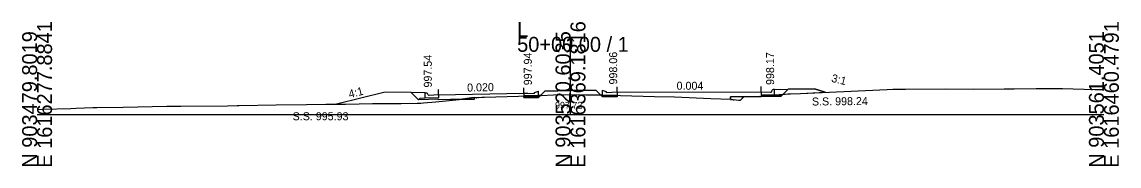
# Model space of a CAD drawing. Extents: x 1009 to 7438, y -1586 to 7964.
# Drawn here: x 4032.1 to 4237.7, y 7914 to 7941.1 of the extents above; entities that cross this region are included whole.
import ezdxf

# ---------------------------------------------------------------- set-up
doc = ezdxf.new("R2010")
doc.units = 0
for name, color, linetype in [('Exist Cross Section Cell', 7, 'Continuous'), ('Exist XS Center Line Elevation Label', 7, 'Continuous'), ('Exist XS Ground Line', 7, 'Continuous'), ('Prop XS Dump Level', 7, 'Continuous'), ('Prop XS Earthwork Shape', 7, 'Continuous'), ('Prop XS EOT Tick Mark', 7, 'Continuous'), ('Prop XS Finish Grade', 7, 'Continuous'), ('Prop XS Finish Grade CurbGutter', 7, 'Continuous'), ('Prop XS Finish Grade Earthwork', 7, 'Continuous'), ('Prop XS Finish Grade Pavement', 7, 'Continuous'), ('Prop XS Hydro Elevations', 7, 'Continuous'), ('Prop XS Pvmt Edge Slope', 7, 'Continuous'), ('Prop XS SE Text', 7, 'Continuous'), ('Prop XS Side Slope Text', 7, 'Continuous'), ('Prop XS SS Elevation Text', 7, 'Continuous'), ('Prop XS Subgrade CurbGutter', 7, 'Continuous'), ('Prop XS Subgrade Earthwork', 7, 'Continuous')]:
    doc.layers.add(name, color=color, linetype=linetype)

msp = doc.modelspace()

# ---------------------------------------------------------------- linework, layer by layer
at = {"layer": 'Exist Cross Section Cell'}
for p, q in [((4134.89, 7923.73), (4134.89, 7938.27)), ((4034.89, 7923.73), (4134.89, 7923.73)), ((4134.89, 7923.73), (4234.89, 7923.73))]:
    msp.add_line(p, q, dxfattribs=at)
at = {"layer": 'Exist XS Ground Line'}
for p, q in [((4118.25, 7926.96), (4118.77, 7926.98)), ((4118.77, 7926.98), (4129.4, 7927.3)), ((4129.4, 7927.3), (4131.69, 7927.38)), ((4131.69, 7927.38), (4134.7, 7927.45)), ((4134.7, 7927.45), (4137.78, 7927.43)), ((4137.78, 7927.43), (4139.99, 7927.41)), ((4139.99, 7927.41), (4150.67, 7927.11)), ((4150.67, 7927.11), (4154.36, 7927.02)), ((4154.36, 7927.02), (4161.2, 7926.73)), ((4166.77, 7926.4), (4167.4, 7927.06)), ((4167.4, 7927.06), (4170.39, 7927.17)), ((4170.39, 7927.17), (4172.79, 7927.25)), ((4172.79, 7927.25), (4175.66, 7927.56)), ((4175.66, 7927.56), (4176.13, 7927.61)), ((4176.13, 7927.61), (4177.99, 7927.67)), ((4177.99, 7927.67), (4194.28, 7928.43)), ((4194.28, 7928.43), (4195.34, 7928.46)), ((4195.34, 7928.46), (4197.71, 7928.49)), ((4197.71, 7928.49), (4205.23, 7928.51)), ((4205.23, 7928.51), (4210.48, 7928.45)), ((4210.48, 7928.45), (4216.19, 7928.5)), ((4216.19, 7928.5), (4218.05, 7928.51)), ((4218.05, 7928.51), (4222.22, 7928.57)), ((4222.22, 7928.57), (4227.14, 7928.58)), ((4227.14, 7928.58), (4233.19, 7928.42)), ((4233.19, 7928.42), (4234.89, 7928.42)), ((4042.22, 7924.89), (4045.33, 7925.01)), ((4045.33, 7925.01), (4046.06, 7925.03)), ((4046.06, 7925.03), (4051.04, 7925.1)), ((4051.04, 7925.1), (4059.21, 7925.26)), ((4059.21, 7925.26), (4061.86, 7925.29)), ((4061.86, 7925.29), (4070.61, 7925.36)), ((4070.61, 7925.36), (4072.4, 7925.4)), ((4072.4, 7925.4), (4072.75, 7925.4)), ((4072.75, 7925.4), (4079.72, 7925.52)), ((4079.72, 7925.52), (4085.37, 7925.6)), ((4085.37, 7925.6), (4089.03, 7925.63)), ((4089.03, 7925.63), (4092.7, 7925.67)), ((4092.7, 7925.67), (4095.28, 7925.7)), ((4095.28, 7925.7), (4097.76, 7925.76)), ((4097.76, 7925.76), (4103.12, 7925.8)), ((4103.12, 7925.8), (4106.15, 7925.81)), ((4106.15, 7925.81), (4106.81, 7925.84)), ((4106.81, 7925.84), (4107.33, 7925.88)), ((4107.33, 7925.88), (4109.67, 7926.08)), ((4109.67, 7926.08), (4114.62, 7926.57)), ((4114.62, 7926.57), (4115.43, 7926.71)), ((4115.43, 7926.71), (4116.32, 7926.81)), ((4116.32, 7926.81), (4116.87, 7926.91)), ((4116.87, 7926.91), (4118.25, 7926.96)), ((4161.2, 7926.73), (4164.91, 7926.61)), ((4164.91, 7926.61), (4166.43, 7926.41)), ((4166.43, 7926.41), (4166.77, 7926.4)), ((4034.89, 7924.66), (4035.88, 7924.69)), ((4035.88, 7924.69), (4041.19, 7924.86)), ((4041.19, 7924.86), (4042.22, 7924.89))]:
    msp.add_line(p, q, dxfattribs=at)
at = {"layer": 'Prop XS Dump Level'}
msp.add_line((4110.14, 7927.39), (4126.14, 7927.71), dxfattribs=at)
msp.add_line((4110.14, 7927.39), (4126.14, 7927.71), dxfattribs=at)
at = {"layer": 'Prop XS Earthwork Shape'}
for points in [[(4109.67, 7926.08), (4114.56, 7926.56), (4110.14, 7926.47), (4110.14, 7926.56), (4106.39, 7926.48), (4105.05, 7927.82), (4100.14, 7927.93), (4091.05, 7925.65), (4092.7, 7925.67), (4095.28, 7925.7), (4097.76, 7925.76), (4103.12, 7925.8), (4106.15, 7925.81), (4106.81, 7925.84), (4107.33, 7925.88)], [(4126.14, 7927.13), (4127.64, 7927.16), (4128.64, 7927.18), (4128.89, 7927.18), (4128.89, 7927.29), (4126.14, 7927.2)], [(4128.64, 7927.18), (4128.89, 7926.93), (4126.14, 7926.88), (4126.14, 7927.13), (4127.64, 7927.16)], [(4128.89, 7926.93), (4129.25, 7927.3), (4128.89, 7927.29), (4128.89, 7927.18), (4128.64, 7927.18)], [(4134.7, 7927.45), (4137.78, 7927.43), (4139.99, 7927.41), (4140.54, 7927.39), (4139.72, 7928.21), (4135, 7928.22), (4130.07, 7928.11), (4129.25, 7927.3), (4129.4, 7927.3), (4131.69, 7927.38)], [(4140.54, 7927.39), (4140.89, 7927.38), (4140.89, 7927.29), (4141.14, 7927.29), (4140.89, 7927.04)], [(4142.14, 7927.29), (4141.14, 7927.29), (4140.89, 7927.29), (4140.89, 7927.38), (4143.64, 7927.31), (4143.64, 7927.29)], [(4143.64, 7927.04), (4140.89, 7927.04), (4141.14, 7927.29), (4142.14, 7927.29), (4143.64, 7927.29)], [(4166.77, 7926.4), (4167.38, 7927.04), (4164.91, 7927.03), (4164.91, 7926.61), (4166.43, 7926.41)], [(4170.64, 7927.14), (4170.64, 7927.06), (4167.38, 7927.04), (4167.4, 7927.06), (4170.39, 7927.17), (4172.79, 7927.25), (4174.04, 7927.39), (4174.14, 7927.39), (4174.39, 7927.14)], [(4174.04, 7927.39), (4174.14, 7927.39), (4174.39, 7927.14), (4174.72, 7927.46)], [(4175.66, 7927.56), (4176.13, 7927.61), (4177.99, 7927.67), (4182.62, 7927.89), (4180.64, 7928.55), (4175.7, 7928.44), (4174.72, 7927.46)], [(4116.87, 7926.61), (4116.87, 7926.91), (4116.32, 7926.81), (4115.43, 7926.71), (4114.62, 7926.57), (4114.56, 7926.56)]]:
    msp.add_lwpolyline(points, close=True, dxfattribs=at)
at = {"layer": 'Prop XS EOT Tick Mark'}
for p, q in [((4110.14, 7927.39), (4110.14, 7928.39)), ((4126.14, 7927.71), (4126.14, 7928.71)), ((4143.64, 7927.87), (4143.64, 7928.87)), ((4170.64, 7927.97), (4170.64, 7928.97))]:
    msp.add_line(p, q, dxfattribs=at)
at = {"layer": 'Prop XS Finish Grade'}
for p, q in [((4107.64, 7927.77), (4105.05, 7927.82)), ((4173.14, 7928.39), (4175.7, 7928.44))]:
    msp.add_line(p, q, dxfattribs=at)
at = {"layer": 'Prop XS Finish Grade CurbGutter'}
for p, q in [((4107.64, 7927.77), (4107.89, 7927.77)), ((4107.89, 7927.77), (4108.02, 7927.74)), ((4108.11, 7927.65), (4108.02, 7927.74)), ((4108.18, 7927.4), (4108.11, 7927.65)), ((4108.27, 7927.31), (4108.18, 7927.4)), ((4108.39, 7927.28), (4108.27, 7927.31)), ((4110.14, 7927.39), (4108.39, 7927.28)), ((4126.14, 7927.71), (4126.89, 7927.69)), ((4126.14, 7927.71), (4128.14, 7927.67)), ((4128.14, 7927.84), (4128.89, 7928.09)), ((4128.14, 7927.67), (4128.14, 7927.84)), ((4141.64, 7927.96), (4140.89, 7928.21)), ((4141.64, 7927.79), (4141.64, 7927.96)), ((4143.64, 7927.87), (4141.64, 7927.79)), ((4143.64, 7927.87), (4142.89, 7927.84)), ((4170.64, 7927.97), (4172.39, 7927.9)), ((4172.39, 7927.9), (4172.52, 7927.92)), ((4172.52, 7927.92), (4172.61, 7928.02)), ((4172.61, 7928.02), (4172.68, 7928.27)), ((4172.68, 7928.27), (4172.77, 7928.36)), ((4172.89, 7928.39), (4172.77, 7928.36)), ((4173.14, 7928.39), (4172.89, 7928.39))]:
    msp.add_line(p, q, dxfattribs=at)
at = {"layer": 'Prop XS Finish Grade Earthwork'}
for p, q in [((4100.14, 7927.93), (4091.05, 7925.65)), ((4105.05, 7927.82), (4100.14, 7927.93)), ((4130.07, 7928.11), (4135, 7928.22)), ((4139.72, 7928.21), (4135, 7928.22)), ((4175.7, 7928.44), (4180.64, 7928.55))]:
    msp.add_line(p, q, dxfattribs=at)
msp.add_lwpolyline([(4180.64, 7928.55), (4182.62, 7927.89)], dxfattribs=at)
at = {"layer": 'Prop XS Finish Grade Pavement'}
for p, q in [((4110.14, 7927.39), (4126.14, 7927.71)), ((4143.64, 7927.87), (4170.64, 7927.97))]:
    msp.add_line(p, q, dxfattribs=at)
at = {"layer": 'Prop XS Pvmt Edge Slope'}
for p, q in [((4127.64, 7927.16), (4128.89, 7927.18)), ((4128.64, 7927.18), (4128.89, 7926.93)), ((4141.14, 7927.29), (4140.89, 7927.04)), ((4142.14, 7927.29), (4140.89, 7927.29)), ((4173.14, 7927.39), (4174.14, 7927.39)), ((4174.14, 7927.39), (4174.39, 7927.14)), ((4106.64, 7926.74), (4106.39, 7926.48)), ((4107.64, 7926.76), (4106.64, 7926.74))]:
    msp.add_line(p, q, dxfattribs=at)
at = {"layer": 'Prop XS Subgrade CurbGutter'}
for p, q in [((4107.64, 7926.76), (4107.64, 7927.77)), ((4110.14, 7927.39), (4110.14, 7926.81)), ((4126.14, 7927.71), (4126.14, 7927.13)), ((4126.14, 7927.13), (4127.64, 7927.16)), ((4128.89, 7927.18), (4128.89, 7928.09)), ((4140.89, 7927.29), (4140.89, 7928.21)), ((4143.64, 7927.29), (4142.14, 7927.29)), ((4143.64, 7927.87), (4143.64, 7927.29)), ((4170.64, 7927.97), (4170.64, 7927.39)), ((4170.64, 7927.39), (4173.14, 7927.39)), ((4173.14, 7927.39), (4173.14, 7928.39)), ((4110.14, 7926.81), (4107.64, 7926.76))]:
    msp.add_line(p, q, dxfattribs=at)
at = {"layer": 'Prop XS Subgrade Earthwork'}
for p, q in [((4106.39, 7926.48), (4105.05, 7927.82)), ((4126.14, 7926.88), (4126.14, 7927.2)), ((4128.89, 7926.93), (4130.07, 7928.11)), ((4140.89, 7927.04), (4139.72, 7928.21)), ((4143.64, 7927.04), (4140.89, 7927.04)), ((4143.64, 7927.04), (4143.64, 7927.31)), ((4164.91, 7927.03), (4170.64, 7927.06)), ((4164.91, 7926.61), (4164.91, 7927.03)), ((4170.64, 7927.14), (4170.64, 7927.06)), ((4170.64, 7927.14), (4174.39, 7927.14)), ((4174.39, 7927.14), (4175.7, 7928.44)), ((4110.14, 7926.56), (4106.39, 7926.48)), ((4116.87, 7926.61), (4110.14, 7926.47)), ((4110.14, 7926.47), (4110.14, 7926.56)), ((4116.87, 7926.61), (4116.87, 7926.91)), ((4116.87, 7926.61), (4116.87, 7926.91)), ((4126.14, 7926.88), (4128.89, 7926.93))]:
    msp.add_line(p, q, dxfattribs=at)

# ---------------------------------------------------------------- texts
at = {"layer": 'Exist Cross Section Cell'}
for s, p in [('E 1616277.8841', (4037.69, 7913.73)), ('E 1616369.1816', (4137.69, 7913.73)), ('E 1616460.4791', (4237.69, 7913.73)), ('N 903479.8019', (4034.89, 7913.73)), ('N 903520.6035', (4134.89, 7913.73)), ('N 903561.4051', (4234.89, 7913.73))]:
    msp.add_text(s, height=2.8, rotation=90, dxfattribs=at).set_placement(p)
for s, p in [('L', (4124.89, 7938.27)), ('50+00.00 / 1', (4124.89, 7935.47))]:
    msp.add_text(s, height=2.8, dxfattribs=at).set_placement(p)
at = {"layer": 'Exist XS Center Line Elevation Label'}
msp.add_text('997.72', height=1.25, dxfattribs=at).set_placement((4131.99, 7924.83))
at = {"layer": 'Prop XS Dump Level'}
for p in [(4116.87, 7926.61), (4116.87, 7926.61), (4116.87, 7926.61), (4164.91, 7926.31)]:
    msp.add_text('Eop', height=0.3, dxfattribs=at).set_placement(p)
at = {"layer": 'Prop XS Hydro Elevations'}
for s, p in [('997.94', (4127.64, 7929.19)), ('998.06', (4143.64, 7929.34)), ('998.17', (4173.06, 7929.25)), ('997.54', (4108.89, 7928.77))]:
    msp.add_text(s, height=1.5, rotation=90, dxfattribs=at).set_placement(p)
at = {"layer": 'Prop XS SE Text'}
for s, rotation, p in [('0.020', 1.1458, (4115.52, 7928)), ('0.004', 359.8864, (4154.78, 7928.36))]:
    msp.add_text(s, height=1.5, rotation=rotation, dxfattribs=at).set_placement(p)
at = {"layer": 'Prop XS Side Slope Text'}
for s, rotation, p in [('3:1', 345.9638, (4183.7, 7929.87)), ('4:1', 14.0362, (4093.48, 7926.77))]:
    msp.add_text(s, height=1.5, rotation=rotation, dxfattribs=at).set_placement(p)
at = {"layer": 'Prop XS SS Elevation Text'}
msp.add_text('S.S. 998.24', height=1.5, rotation=0.5729, dxfattribs=at).set_placement((4180.16, 7925.39))
msp.add_text('S.S. 995.93', height=1.5, dxfattribs=at).set_placement((4082.79, 7922.63))

doc.saveas('drawing.dxf')
